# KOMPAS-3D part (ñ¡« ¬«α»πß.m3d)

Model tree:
1. Эскиз:1
2. Операция выдавливания:1
     Расстояние 1 = 0.2
3. Эскиз:3
4. Операция выдавливания:2
     Расстояние 1 = 4.8
5. Эскиз:4
6. Операция выдавливания:3
     Расстояние 1 = 2.5
7. Зеркальный массив:2  (with: Операция выдавливания:1, Операция выдавливания:2, Операция выдавливания:3)  (labels: Экземпляр ( 1 ); Экземпляр ( 2 ))
8. Фаска:1
     Угол = 77.4712; Длина 1 = 2; Длина 2 = 9
9. Фаска:2
     Угол = 12.5288; Длина 1 = 9; Длина 2 = 2
10. Скругление:34
     Радиус = 1
11. Скругление:37
     Радиус = 2
12. Скругление:38
     Радиус = 0.5
13. Скругление:39
     Радиус = 1
14. Эскиз:23
15. Операция выдавливания:11
     Расстояние 1 = 2
16. Скругление:40
     Радиус = 1.5
17. Скругление:41
     Радиус = 1.5
18. Эскиз:24
19. Операция выдавливания:12
     Расстояние 1 = 1
20. Эскиз:25
21. Вырезать элемент выдавливания:12
     Расстояние 1 = 10
22. Эскиз:26
23. Операция выдавливания:13
     Расстояние 1 = 3
24. Эскиз:27
25. Вырезать элемент выдавливания:13
     Расстояние 1 = 0.5
26. Эскиз:28
27. Вырезать элемент выдавливания:14
     Расстояние 1 = 0.5
28. Эскиз:29
29. Операция выдавливания:14
     Расстояние 1 = 2
30. Эскиз:30
31. Операция выдавливания:15
     Расстояние 1 = 5; Угол 1 = 20
32. Скругление:42
     Радиус = 1.5
33. Скругление:43
     Радиус = 1.5
34. Скругление:44
     Радиус = 1.5
35. Скругление:45
     Радиус = 1.5
36. Скругление:46
     Радиус = 1.5
37. Скругление:47
     Радиус = 0.5
38. Скругление:48
     Радиус = 0.5
39. Скругление:49
     Радиус = 0.5
40. Эскиз:31
41. Операция выдавливания:16
     Расстояние 1 = 2; Угол 1 = 20
42. Эскиз:32
43. Вырезать элемент выдавливания:15
     Расстояние 2 = 64.0611; Расстояние 1 = 64
44. Эскиз:33
45. Вырезать элемент выдавливания:16
     Расстояние 1 = 0.5
46. Эскиз:34
47. Вырезать элемент выдавливания:17
     Расстояние 1 = 0.5
48. Скругление:51
     Радиус = 1
49. Скругление:52
     Радиус = 1
50. Скругление:53
     Радиус = 1
51. Скругление:54
     Радиус = 1
52. Скругление:55
     Радиус = 0.5
53. Скругление:56
     Радиус = 0.5
54. Скругление:57
     Радиус = 0.5
55. Скругление:58
     Радиус = 1
56. Скругление:59
     Радиус = 1
57. Скругление:60
     Радиус = 0.5
58. Скругление:61
     Радиус = 2
59. Скругление:62
     Радиус = 2
60. Скругление:63
     Радиус = 0.2
61. Скругление:64
     Радиус = 0.5

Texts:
  stalker61
  Сплав АЛ8  ГОСТ 1583-93
  Экземпляр ( 1 )
  Экземпляр ( 2 )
